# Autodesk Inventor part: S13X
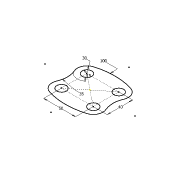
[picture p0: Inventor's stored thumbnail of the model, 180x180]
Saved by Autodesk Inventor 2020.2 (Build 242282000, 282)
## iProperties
Created: 2016-06
Part Number: S13X
Material: Ogólny
Document SubType Name: Modeling
Designer: F.Stasiak
Density: 1 g/cm^3
Appearance: Domyślna
Manager: www.cadconsulting.pl
Company: Fabian Stasiak CAD Consulting
Author: F.Stasiak
Subject: Zbiór ćwiczeń. Autodesk Inventor 2020. Kurs podstawowy
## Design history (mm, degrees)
sketch "Szkic1"
  geometry: L1 (-25, 20)-(25, 20); L2 (25, 20)-(25, -20); L3 (25, -20)-(-25, -20); L4 (-25, -20)-(-25, 20); L5 (-25, 20)-(25, -20); L6 (25, 20)-(-25, -20); C1 r 7.5 at (-25, 20); C2 r 7.5 at (25, 20); C3 r 7.5 at (-25, -20); C4 r 7.5 at (25, -20); A1 r 15 centre (-25, 20) between (-29.412, 34.337) and (-38.748, 14); A2 r 15 centre (25, 20) between (38.748, 14) and (29.412, 34.337); A3 r 15 centre (-25, -20) between (-38.748, -14) and (-29.412, -34.337); A4 r 15 centre (25, -20) between (29.412, -34.337) and (38.748, -14); A5 r 100 centre (0, -61.24) between (29.412, 34.337) and (-29.412, 34.337); A6 r 100 centre (0, 61.24) between (-29.412, -34.337) and (29.412, -34.337); A7 r 35 centre (-70.826, 0) between (-38.748, -14) and (-38.748, 14); A8 r 35 centre (70.826, 0) between (38.748, 14) and (38.748, -14); 1 further point
  constraints: 16 point on circle, 12 centre point, 12 end point, 8 coincident, 8 equal radius, 8 tangent, 2 midpoint, 2 parallel, 1 horizontal, 1 perpendicular
  dimensions: "d0" = 50 distance of L2.end L3.end; "d1" = 40 distance of L1.end L2.end; "d2" = 15 diameter of C1; "d3" = 30 diameter of A1; "d4" = 100 radius of A5; "d5" = 35 radius of A7
